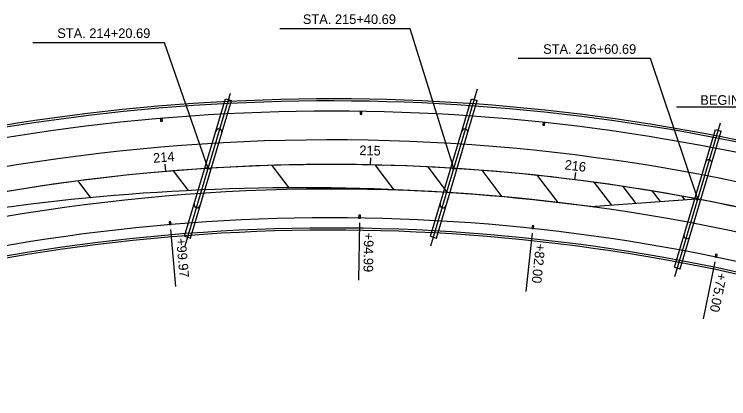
# Model space of a CAD drawing. Extents: x 10803 to 14007, y 6159 to 7440.
# Drawn here: x 12371.6 to 12720.1, y 6616 to 6803.4 of the extents above; entities that cross this region are included whole.
import ezdxf

# ---------------------------------------------------------------- set-up
doc = ezdxf.new("R2010")
doc.units = 0
for name, color, linetype in [('BR_X_Drain_Object', 7, 'Continuous'), ('BR_X_Rail_Object', 7, 'Continuous'), ('BR_X_Slab_Object', 7, 'Continuous'), ('BR_X_Sub_Object', 7, 'Continuous'), ('Default', 7, 'Continuous'), ('GE_X_Alignment', 7, 'Continuous'), ('GE_X_Alignment_100_Stations', 7, 'Continuous'), ('PM_X_CL_Double_Solid', 7, 'Continuous'), ('PM_X_Lane_Line', 7, 'Continuous'), ('PM_X_Transverse_Line', 7, 'Continuous'), ('SC_Scratch1', 7, 'Continuous')]:
    doc.layers.add(name, color=color, linetype=linetype)

msp = doc.modelspace()

# ---------------------------------------------------------------- linework, layer by layer
at = {"layer": 'BR_X_Drain_Object'}
for points in [[(12540.32, 6754.75), (12541.15, 6754.74), (12541.17, 6756.07), (12540.34, 6756.08)], [(12442.96, 6751.32), (12443.8, 6751.39), (12443.68, 6752.72), (12442.85, 6752.65)], [(12629.37, 6749.39), (12630.2, 6749.3), (12630.34, 6750.63), (12629.51, 6750.71)], [(12539.55, 6704.09), (12540.39, 6704.08), (12540.41, 6705.41), (12539.57, 6705.42)], [(12447.22, 6700.83), (12448.05, 6700.9), (12447.94, 6702.23), (12447.11, 6702.16)], [(12624.01, 6699.01), (12624.84, 6698.91), (12624.99, 6700.24), (12624.16, 6700.34)], [(12713.37, 6685.11), (12714.18, 6684.94), (12714.45, 6686.24), (12713.64, 6686.41)]]:
    msp.add_lwpolyline(points, close=True, dxfattribs=at)
at = {"layer": 'BR_X_Rail_Object'}
for radius, start, end in [(986.93, 73.39646, 105.444), (985.93, 73.44, 105.39238), (923.93, 73.39349, 107.88018), (922.93, 73.39344, 107.88024)]:
    msp.add_arc((12526.06, 5775.26), radius, start, end, dxfattribs=at)
at = {"layer": 'BR_X_Slab_Object'}
for radius, start, end in [(980.93, 73.3962, 105.57342), (928.93, 73.5225, 107.61257)]:
    msp.add_arc((12526.06, 5775.26), radius, start, end, dxfattribs=at)
at = {"layer": 'BR_X_Sub_Object'}
for p, q in [((12454.68, 6695.18), (12474.63, 6762.28)), ((12457.56, 6694.33), (12477.51, 6761.42)), ((12474.63, 6762.28), (12477.51, 6761.42)), ((12574.6, 6695.18), (12594.55, 6762.28)), ((12577.48, 6694.33), (12597.43, 6761.42)), ((12594.55, 6762.28), (12597.43, 6761.42)), ((12693.58, 6680.15), (12713.53, 6747.25)), ((12696.45, 6679.3), (12716.4, 6746.39)), ((12713.53, 6747.25), (12716.4, 6746.39)), ((12454.68, 6695.18), (12457.56, 6694.33)), ((12574.6, 6695.18), (12577.48, 6694.33)), ((12693.58, 6680.15), (12696.45, 6679.3))]:
    msp.add_line(p, q, dxfattribs=at)
for centre, start, end in [((12471.37, 6746.04), 73.4407, 163.4399), ((12471.37, 6746.03), 343.4399, 73.4419), ((12591.29, 6746.04), 73.4407, 163.4399), ((12591.29, 6746.03), 343.4399, 73.4419), ((12710.26, 6731.01), 73.4407, 163.4399), ((12710.27, 6731), 343.4399, 73.4419), ((12460.82, 6710.57), 163.4399, 253.4407), ((12460.82, 6710.57), 253.4395, 343.4399), ((12580.74, 6710.57), 163.4399, 253.4407), ((12580.74, 6710.57), 253.4395, 343.4399), ((12699.72, 6695.54), 163.4399, 253.4407), ((12699.72, 6695.54), 253.4395, 343.4399)]:
    msp.add_arc(centre, 1.5, start, end, dxfattribs=at)
at = {"layer": 'Default'}
for p, q in [((12454.88, 6690.58), (12477.02, 6765.03)), ((12574.8, 6690.58), (12597.55, 6767.07)), ((12693.77, 6675.55), (12716.05, 6750.48)), ((12471.79, 6747.47), (12471.8, 6747.47)), ((12591.72, 6747.47), (12591.72, 6747.47)), ((12710.69, 6732.44), (12710.69, 6732.44)), ((12464.66, 6728.73), (12467.53, 6727.87)), ((12465.44, 6728.2), (12465.44, 6728.2)), ((12584.58, 6728.73), (12587.45, 6727.87)), ((12585.36, 6728.2), (12585.36, 6728.2)), ((12703.55, 6713.7), (12706.43, 6712.84)), ((12704.34, 6713.17), (12704.34, 6713.17)), ((12460.4, 6709.13), (12460.4, 6709.13)), ((12580.32, 6709.13), (12580.32, 6709.13)), ((12699.29, 6694.1), (12699.29, 6694.1))]:
    msp.add_line(p, q, dxfattribs=at)
for points in [[(12586.02, 6728.3), (12564.7, 6796.35), (12501.17, 6796.35)], [(12466.1, 6728.3), (12444.82, 6789.53), (12380.61, 6789.53)], [(12704.99, 6713.27), (12681.85, 6781.81), (12617.42, 6781.81)], [(12800.38, 6689.93), (12778.07, 6758.21), (12694.59, 6758.21)]]:
    msp.add_lwpolyline(points, dxfattribs=at)
for centre, start, end in [((12465.03, 6733.09), 274.7857, 282.5401), ((12468.27, 6723.9), 116.2654, 124.0199), ((12584.95, 6733.09), 274.7857, 282.5401), ((12588.19, 6723.9), 116.2654, 124.0199), ((12703.93, 6718.06), 274.7857, 282.5401), ((12707.16, 6708.87), 116.2654, 124.0199)]:
    msp.add_arc(centre, 4.91, start, end, dxfattribs=at)
for centre in [(12465.4, 6728.06), (12585.32, 6728.06), (12704.29, 6713.03)]:
    msp.add_ellipse(centre, major_axis=(0.157, 0.055), ratio=0.873734, start_param=5.258637, end_param=7.300638, dxfattribs=at)
at = {"layer": 'GE_X_Alignment'}
msp.add_arc((12526.06, 5775.26), 954.93, 61.68982, 109.40279, dxfattribs=at)
at = {"layer": 'GE_X_Alignment_100_Stations'}
for p, q in [((12545.36, 6729.99), (12545.44, 6733.5)), ((12445.46, 6726.78), (12445.17, 6730.28)), ((12645.06, 6722.74), (12645.49, 6726.22))]:
    msp.add_line(p, q, dxfattribs=at)
at = {"layer": 'PM_X_CL_Double_Solid'}
msp.add_line((12652.73, 6709.64), (12704.31, 6713.4), dxfattribs=at)
for centre, radius, start, end in [((12526.05, 5775.09), 955.1, 82.24238, 109.59751), ((12511.51, 5634.46), 1084.41, 82.51751, 106.38015), ((12526.06, 5775.26), 954.93, 70.84141, 82.24143)]:
    msp.add_arc(centre, radius, start, end, dxfattribs=at)
at = {"layer": 'PM_X_Lane_Line'}
for radius in [966.93, 942.93]:
    msp.add_arc((12526.06, 5775.26), radius, 70.8415, 109.40281, dxfattribs=at)
at = {"layer": 'PM_X_Transverse_Line'}
for p, q in [((12497.27, 6729.75), (12505.56, 6718.86)), ((12547.39, 6729.95), (12556.53, 6717.94)), ((12573.23, 6729.02), (12582.74, 6716.53)), ((12449.04, 6727.07), (12456.35, 6717.47)), ((12599.64, 6727.35), (12609.47, 6714.44)), ((12402.51, 6722.16), (12408.72, 6713.99)), ((12626.66, 6724.87), (12636.75, 6711.62)), ((12654.34, 6721.53), (12662.83, 6710.38)), ((12668.44, 6719.51), (12674.74, 6711.24)), ((12682.74, 6717.24), (12686.64, 6712.11)), ((12697.23, 6714.72), (12698.55, 6712.98))]:
    msp.add_line(p, q, dxfattribs=at)
at = {"layer": 'SC_Scratch1'}
for p, q in [((12539.93, 6701.74), (12539.51, 6673.7)), ((12447.83, 6698.53), (12450.18, 6670.77)), ((12624.17, 6696.64), (12621.15, 6668.2)), ((12713.3, 6682.73), (12707.57, 6654.98))]:
    msp.add_line(p, q, dxfattribs=at)

# ---------------------------------------------------------------- texts
at = {"layer": 'Default'}
for s, p in [('STA. 215+40.69', (12512.34, 6798.69)), ('STA. 214+20.69', (12392.54, 6791.87)), ('STA. 216+60.69', (12629.53, 6784.15)), ('BEGIN APPROACH SLAB', (12706.19, 6759.29))]:
    msp.add_text(s, height=4.68, dxfattribs=at).set_placement(p)
at = {"layer": 'GE_X_Alignment_100_Stations'}
for s, rotation, p in [('215', 358.8415, (12539.85, 6734.78)), ('214', 4.8414, (12439.5, 6730.97)), ('216', 352.8414, (12639.8, 6727.85))]:
    msp.add_text(s, height=4.68, rotation=rotation, dxfattribs=at).set_placement(p)
at = {"layer": 'SC_Scratch1'}
for s, rotation, p in [('+94.99', 269.1418, (12542.2, 6697.03)), ('+99.97', 274.8431, (12450.56, 6694.07)), ('+82.00', 263.9219, (12626.01, 6691.73)), ('+75.00', 258.3418, (12714.65, 6677.67))]:
    msp.add_text(s, height=4.68, rotation=rotation, dxfattribs=at).set_placement(p)

doc.saveas('drawing.dxf')
